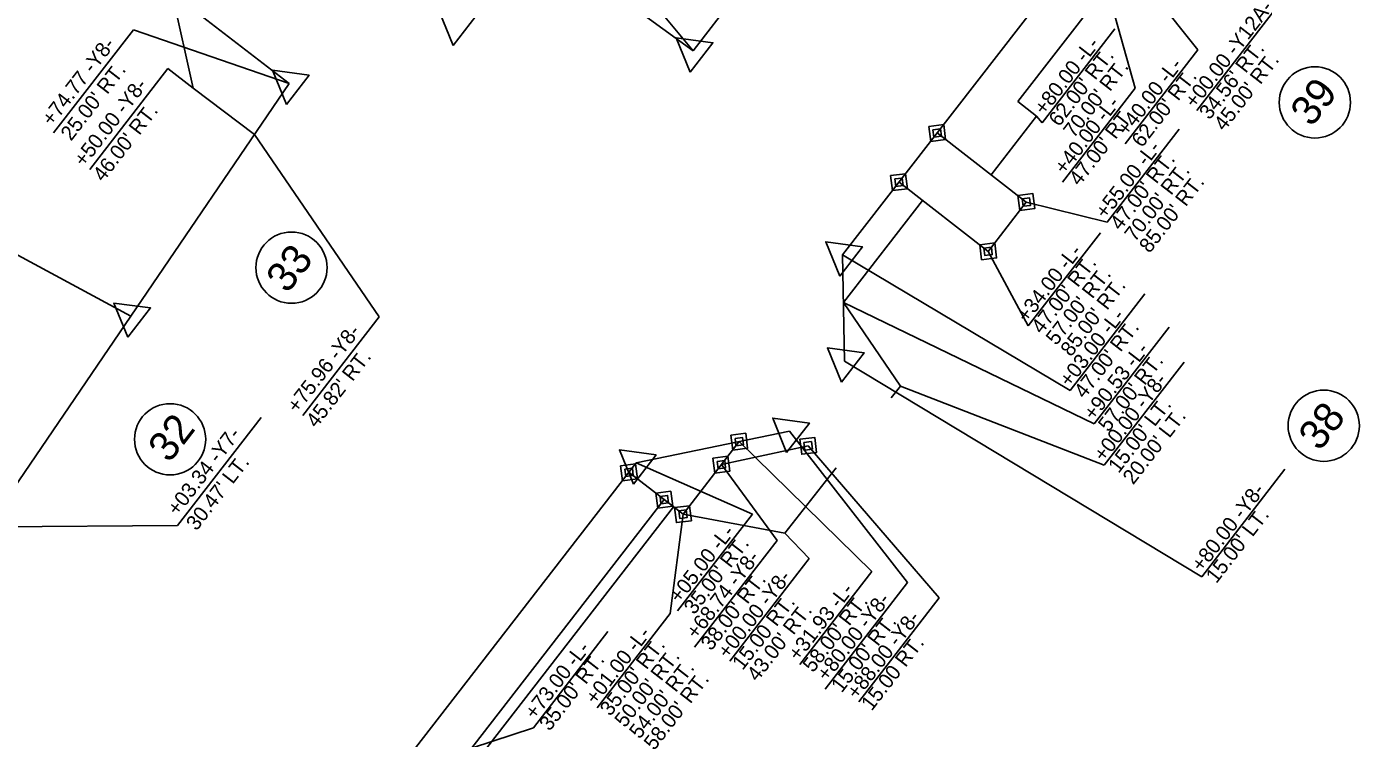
# Model space of a CAD drawing. Extents: x 2010883 to 2014849, y 442000 to 447413.
# Drawn here: x 2014399.8 to 2014849, y 445727.9 to 445967.7 of the extents above; entities that cross this region are included whole.
import ezdxf

# ---------------------------------------------------------------- set-up
doc = ezdxf.new("R2010")
doc.units = 0
for name, color, linetype in [('Prop Easement Construction', 7, 'Continuous'), ('Prop Easement Construction Station Offsets', 7, 'Continuous'), ('Prop Easement Permanent Drainage Station Offsets', 7, 'Continuous'), ('Prop Easement Permanent Drainage Utility', 7, 'Continuous'), ('Prop Easement Permanent Utility', 7, 'Continuous'), ('Prop Easement Permanent Utility Station Offsets', 7, 'Continuous'), ('Prop Parcel Number CELL', 7, 'Continuous'), ('Prop Parcel Number Text', 7, 'Continuous'), ('Prop ROW Marker CELL', 7, 'Continuous'), ('Prop ROW Permanent Easement CELL', 7, 'Continuous'), ('Prop ROW RW Lines', 7, 'Continuous'), ('Prop ROW Station Offsets', 7, 'Continuous')]:
    doc.layers.add(name, color=color, linetype=linetype)

msp = doc.modelspace()

# ---------------------------------------------------------------- linework, layer by layer
at = {"layer": 'Prop Easement Construction'}
for p, q in [((2014733.85, 445942.42), (2014770.62, 445989.83)), ((2014455.84, 445946.99), (2014448.82, 445978.88)), ((2014476.54, 445931.31), (2014455.84, 445946.99)), ((2014740.17, 445937.52), (2014733.85, 445942.42)), ((2014724.85, 445917.76), (2014740.17, 445937.52)), ((2014675.06, 445874.78), (2014701.7, 445909.13)), ((2014694.26, 445846.56), (2014675.06, 445874.78)), ((2014691.16, 445842.63), (2014694.26, 445846.56)), ((2014655.27, 445797.07), (2014672.6, 445819.07)), ((2014539.38, 445704.73), (2014617.83, 445805.87)), ((2014620.99, 445803.42), (2014655.27, 445797.07))]:
    msp.add_line(p, q, dxfattribs=at)
at = {"layer": 'Prop Easement Construction Station Offsets'}
for p, q in [((2014794.51, 445959.85), (2014770.62, 445989.83)), ((2014742.06, 445935.28), (2014766.58, 445966.89)), ((2014770, 445928.24), (2014794.51, 445959.85)), ((2014421.02, 445919.54), (2014447.37, 445953.52)), ((2014455.84, 445946.99), (2014447.37, 445953.52)), ((2014742.06, 445935.28), (2014740.17, 445937.52)), ((2014518.56, 445869.89), (2014476.54, 445931.31)), ((2014759.6, 445833.86), (2014675.06, 445874.78)), ((2014492.82, 445836.7), (2014518.56, 445869.89)), ((2014759.6, 445833.86), (2014784.83, 445866.39)), ((2014762.98, 445819.95), (2014789.91, 445854.67)), ((2014762.98, 445819.95), (2014694.26, 445846.56)), ((2014450.66, 445799.63), (2014478.85, 445835.98)), ((2014707.38, 445775.24), (2014663.19, 445826.46)), ((2014616.66, 445769.92), (2014620.99, 445803.42)), ((2014386.46, 445799.12), (2014450.66, 445799.63)), ((2014663.5, 445788.44), (2014655.27, 445797.07)), ((2014636.75, 445753.95), (2014663.5, 445788.44)), ((2014680.24, 445740.26), (2014707.38, 445775.24)), ((2014592.02, 445738.15), (2014616.66, 445769.92))]:
    msp.add_line(p, q, dxfattribs=at)
at = {"layer": 'Prop Easement Permanent Drainage Station Offsets'}
for p in [(2014639.94, 445827.86), (2014660.36, 445752.83)]:
    msp.add_line(p, (2014684.64, 445784.14), dxfattribs=at)
at = {"layer": 'Prop Easement Permanent Drainage Utility'}
for p, q in [((2014620.99, 445803.42), (2014639.94, 445827.86)), ((2014602.81, 445817.52), (2014620.99, 445803.42))]:
    msp.add_line(p, q, dxfattribs=at)
at = {"layer": 'Prop Easement Permanent Utility'}
for p, q in [((2014736.7, 445908.57), (2014706.67, 445931.86)), ((2014693.8, 445915.26), (2014723.83, 445891.97)), ((2014723.83, 445891.97), (2014736.7, 445908.57)), ((2014633.94, 445820.12), (2014663.19, 445826.46)), ((2014527.22, 445695.57), (2014614.67, 445808.33))]:
    msp.add_line(p, q, dxfattribs=at)
at = {"layer": 'Prop Easement Permanent Utility Station Offsets'}
for p, q in [((2014763.9, 445901.79), (2014788.18, 445933.09)), ((2014763.9, 445901.79), (2014736.7, 445908.57)), ((2014737.38, 445866.9), (2014761.66, 445898.2)), ((2014737.38, 445866.9), (2014723.83, 445891.97))]:
    msp.add_line(p, q, dxfattribs=at)
at = {"layer": 'Prop Parcel Number CELL'}
for p, q in [((2014833.96, 445942.15), (2014833.96, 445942.15)), ((2014489.04, 445886.48), (2014489.04, 445886.48)), ((2014836.95, 445833.23), (2014836.95, 445833.23)), ((2014448.12, 445828.65), (2014448.12, 445828.65))]:
    msp.add_line(p, q, dxfattribs=at)
for centre in [(2014833.96, 445942.15), (2014489.04, 445886.48), (2014836.95, 445833.23), (2014448.12, 445828.65)]:
    msp.add_circle(centre, 12, dxfattribs=at)
at = {"layer": 'Prop ROW Marker CELL'}
for p, q in [((2014624.37, 445959.54), (2014624.37, 445959.54)), ((2014488.28, 445948.55), (2014488.28, 445948.55)), ((2014706.67, 445931.86), (2014706.67, 445931.86)), ((2014693.8, 445915.26), (2014693.8, 445915.26)), ((2014736.7, 445908.57), (2014736.7, 445908.57)), ((2014674.8, 445890.77), (2014674.8, 445890.77)), ((2014723.83, 445891.97), (2014723.83, 445891.97)), ((2014434.87, 445870.16), (2014434.87, 445870.16)), ((2014675.38, 445855.01), (2014675.38, 445855.01)), ((2014656.91, 445831.38), (2014656.91, 445831.38)), ((2014639.94, 445827.86), (2014639.94, 445827.86)), ((2014663.19, 445826.46), (2014663.19, 445826.46)), ((2014602.81, 445817.52), (2014602.81, 445817.52)), ((2014602.81, 445817.52), (2014602.81, 445817.52)), ((2014605.26, 445820.68), (2014605.26, 445820.68)), ((2014633.94, 445820.12), (2014633.94, 445820.12)), ((2014614.67, 445808.33), (2014614.67, 445808.33)), ((2014620.99, 445803.42), (2014620.99, 445803.42))]:
    msp.add_line(p, q, dxfattribs=at)
for points in [[(2014543.47, 445961.3), (2014538.77, 445972.85), (2014551.13, 445971.17)], [(2014623.39, 445952.39), (2014618.68, 445963.95), (2014631.05, 445962.27)], [(2014487.3, 445941.4), (2014482.59, 445952.96), (2014494.96, 445951.28)], [(2014673.82, 445883.62), (2014669.12, 445895.18), (2014681.48, 445893.5)], [(2014433.88, 445863.02), (2014429.18, 445874.57), (2014441.54, 445872.89)], [(2014674.4, 445847.87), (2014669.69, 445859.43), (2014682.06, 445857.75)], [(2014655.93, 445824.23), (2014651.22, 445835.79), (2014663.59, 445834.11)], [(2014604.28, 445813.53), (2014599.57, 445825.09), (2014611.94, 445823.41)]]:
    msp.add_lwpolyline(points, close=True, dxfattribs=at)
at = {"layer": 'Prop ROW Permanent Easement CELL'}
for points in [[(2014703.83, 445934.06), (2014708.88, 445934.7), (2014709.52, 445929.65), (2014704.47, 445929.01)], [(2014705.25, 445932.96), (2014707.78, 445933.28), (2014708.09, 445930.75), (2014705.57, 445930.43)], [(2014690.96, 445917.47), (2014696.01, 445918.11), (2014696.65, 445913.06), (2014691.6, 445912.42)], [(2014692.38, 445916.37), (2014694.91, 445916.68), (2014695.22, 445914.16), (2014692.7, 445913.84)], [(2014733.86, 445910.78), (2014738.91, 445911.41), (2014739.54, 445906.36), (2014734.49, 445905.72)], [(2014735.28, 445909.67), (2014737.8, 445909.99), (2014738.12, 445907.47), (2014735.6, 445907.15)], [(2014720.99, 445894.18), (2014726.04, 445894.82), (2014726.67, 445889.77), (2014721.62, 445889.13)], [(2014722.41, 445893.08), (2014724.93, 445893.4), (2014725.25, 445890.87), (2014722.73, 445890.55)], [(2014637.1, 445830.07), (2014642.15, 445830.71), (2014642.78, 445825.66), (2014637.73, 445825.02)], [(2014638.52, 445828.96), (2014641.04, 445829.28), (2014641.36, 445826.76), (2014638.84, 445826.44)], [(2014660.35, 445828.67), (2014665.4, 445829.3), (2014666.04, 445824.25), (2014660.99, 445823.61)], [(2014661.77, 445827.56), (2014664.29, 445827.88), (2014664.61, 445825.36), (2014662.09, 445825.04)], [(2014631.09, 445822.33), (2014636.14, 445822.97), (2014636.78, 445817.92), (2014631.73, 445817.28)], [(2014632.52, 445821.22), (2014635.04, 445821.54), (2014635.36, 445819.02), (2014632.83, 445818.7)], [(2014599.97, 445819.72), (2014605.02, 445820.36), (2014605.66, 445815.31), (2014600.61, 445814.67)], [(2014599.97, 445819.72), (2014605.02, 445820.36), (2014605.66, 445815.31), (2014600.61, 445814.67)], [(2014601.39, 445818.62), (2014603.92, 445818.94), (2014604.23, 445816.42), (2014601.71, 445816.1)], [(2014601.39, 445818.62), (2014603.92, 445818.94), (2014604.23, 445816.42), (2014601.71, 445816.1)], [(2014611.82, 445810.53), (2014616.87, 445811.17), (2014617.51, 445806.12), (2014612.46, 445805.48)], [(2014613.24, 445809.43), (2014615.77, 445809.75), (2014616.09, 445807.22), (2014613.56, 445806.9)], [(2014618.14, 445805.63), (2014623.19, 445806.27), (2014623.83, 445801.22), (2014618.78, 445800.58)], [(2014619.57, 445804.53), (2014622.09, 445804.85), (2014622.41, 445802.32), (2014619.88, 445802)]]:
    msp.add_lwpolyline(points, close=True, dxfattribs=at)
at = {"layer": 'Prop ROW RW Lines'}
for p, q in [((2014624.37, 445959.54), (2014700.09, 446057.18)), ((2014567.88, 446000.94), (2014624.37, 445959.54)), ((2014674.8, 445890.77), (2014758.76, 445999.02)), ((2014448.82, 445978.88), (2014488.28, 445948.55)), ((2014434.87, 445870.16), (2014488.28, 445948.55)), ((2014675.38, 445855.01), (2014674.8, 445890.77)), ((2014380.56, 445790.46), (2014434.87, 445870.16)), ((2014605.26, 445820.68), (2014656.91, 445831.38)), ((2014524.37, 445716.37), (2014605.26, 445820.68))]:
    msp.add_line(p, q, dxfattribs=at)
at = {"layer": 'Prop ROW Station Offsets'}
for p, q in [((2014563.93, 446032.16), (2014624.37, 445959.54)), ((2014773.39, 445946.91), (2014758.76, 445999.02)), ((2014794.16, 445939.46), (2014825.42, 445979.76)), ((2014408.77, 445931.86), (2014435.74, 445966.63)), ((2014435.74, 445966.63), (2014488.28, 445948.55)), ((2014748.87, 445915.31), (2014773.39, 445946.91)), ((2014328.83, 445927.32), (2014434.87, 445870.16)), ((2014751.46, 445845.11), (2014674.8, 445890.77)), ((2014751.46, 445845.11), (2014776.69, 445877.64)), ((2014795.82, 445782.36), (2014675.38, 445855.01)), ((2014696.71, 445780.39), (2014656.91, 445831.38)), ((2014644.39, 445803.41), (2014605.26, 445820.68)), ((2014652.72, 445794.57), (2014633.94, 445820.12)), ((2014795.82, 445782.36), (2014823.87, 445818.54)), ((2014619.15, 445770.86), (2014644.39, 445803.41)), ((2014624.87, 445758.66), (2014652.72, 445794.57)), ((2014668.86, 445744.48), (2014696.71, 445780.39)), ((2014570.56, 445731.5), (2014595.68, 445763.9)), ((2014570.56, 445731.5), (2014524.37, 445716.37))]:
    msp.add_line(p, q, dxfattribs=at)

# ---------------------------------------------------------------- texts
at = {"layer": 'Prop Easement Construction Station Offsets'}
for s, p in [('+80.00 -L-', (2014742.82, 445937.53)), ("62.00' RT.", (2014747.76, 445933.7)), ("70.00' RT.", (2014752.7, 445929.87)), ('+40.00 -L-', (2014770.76, 445930.49)), ("62.00' RT.", (2014775.7, 445926.66)), ('+50.00 -Y8-', (2014419.14, 445920.09)), ("46.00' RT.", (2014425.56, 445915.11)), ('+75.96 -Y8-', (2014490.99, 445837.17)), ("45.82' RT.", (2014497.41, 445832.19)), ('+90.53 -L-', (2014759.47, 445834.68)), ("57.00' RT.", (2014764.41, 445830.85)), ('+00.00 -Y8-', (2014762.85, 445820.76)), ("15.00' LT.", (2014767.79, 445816.93)), ("20.00' LT.", (2014772.73, 445813.1)), ('+03.34 -Y7-', (2014450.61, 445802.56)), ("30.47' LT.", (2014457.03, 445797.58)), ('+00.00 -Y8-', (2014636.14, 445754.42)), ('15.00 RT.', (2014641.08, 445750.59)), ("43.00' RT.", (2014646.02, 445746.75)), ('+88.00 -Y8-', (2014679.64, 445740.72)), ('+01.00 -L-', (2014591.55, 445738.92)), ("35.00' RT.", (2014596.49, 445735.09)), ('15.00 RT.', (2014684.58, 445736.89)), ("50.00' RT.", (2014601.43, 445731.26)), ("54.00' RT.", (2014606.37, 445727.43)), ("58.00' RT.", (2014611.31, 445723.6))]:
    msp.add_text(s, height=5, rotation=52.2051, dxfattribs=at).set_placement(p)
at = {"layer": 'Prop Easement Permanent Drainage Station Offsets'}
for s, p in [('+31.93 -L-', (2014659.9, 445753.62)), ("58.00' RT.", (2014664.84, 445749.79))]:
    msp.add_text(s, height=5, rotation=52.2051, dxfattribs=at).set_placement(p)
at = {"layer": 'Prop Easement Permanent Utility Station Offsets'}
for s, p in [('+55.00 -L-', (2014763.44, 445902.57)), ("47.00' RT.", (2014768.38, 445898.74)), ("70.00' RT.", (2014773.32, 445894.91)), ("85.00' RT.", (2014778.26, 445891.08)), ('+34.00 -L-', (2014736.92, 445867.68)), ("47.00' RT.", (2014741.86, 445863.85)), ("57.00' RT.", (2014746.8, 445860.02)), ("85.00' RT.", (2014751.74, 445856.19))]:
    msp.add_text(s, height=5, rotation=52.2051, dxfattribs=at).set_placement(p)
at = {"layer": 'Prop Parcel Number Text'}
for s, p in [('39', (2014832.87, 445933.55)), ('33', (2014487.63, 445877.48)), ('38', (2014835.6, 445824.34)), ('32', (2014447.85, 445820.37))]:
    msp.add_text(s, height=10, rotation=52.2051, dxfattribs=at).set_placement(p)
at = {"layer": 'Prop ROW Station Offsets'}
for s, p in [('+00.00 -Y12A-', (2014793.54, 445939.86)), ('+74.77 -Y8-', (2014408.32, 445933.87)), ("34.56' RT.", (2014798.48, 445936.03)), ("45.00' RT.", (2014803.42, 445932.2)), ("25.00' RT.", (2014414.74, 445928.89)), ('+40.00 -L-', (2014749.63, 445917.56)), ("47.00' RT.", (2014754.57, 445913.73)), ('+03.00 -L-', (2014751.33, 445845.93)), ("47.00' RT.", (2014756.27, 445842.1)), ('+80.00 -Y8-', (2014795.81, 445783.66)), ("15.00' LT.", (2014800.75, 445779.83)), ('+05.00 -L-', (2014619.86, 445773.15)), ("35.00' RT.", (2014624.8, 445769.32)), ('+68.74 -Y8-', (2014625.54, 445760.98)), ("38.00' RT.", (2014630.48, 445757.15)), ('+80.00 -Y8-', (2014669.53, 445746.8)), ("15.00' RT.", (2014674.47, 445742.97)), ('+73.00 -L-', (2014571.1, 445733.92)), ("35.00' RT.", (2014576.04, 445730.09))]:
    msp.add_text(s, height=5, rotation=52.2051, dxfattribs=at).set_placement(p)

doc.saveas('drawing.dxf')
